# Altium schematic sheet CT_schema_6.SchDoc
size 421 x 246 mm
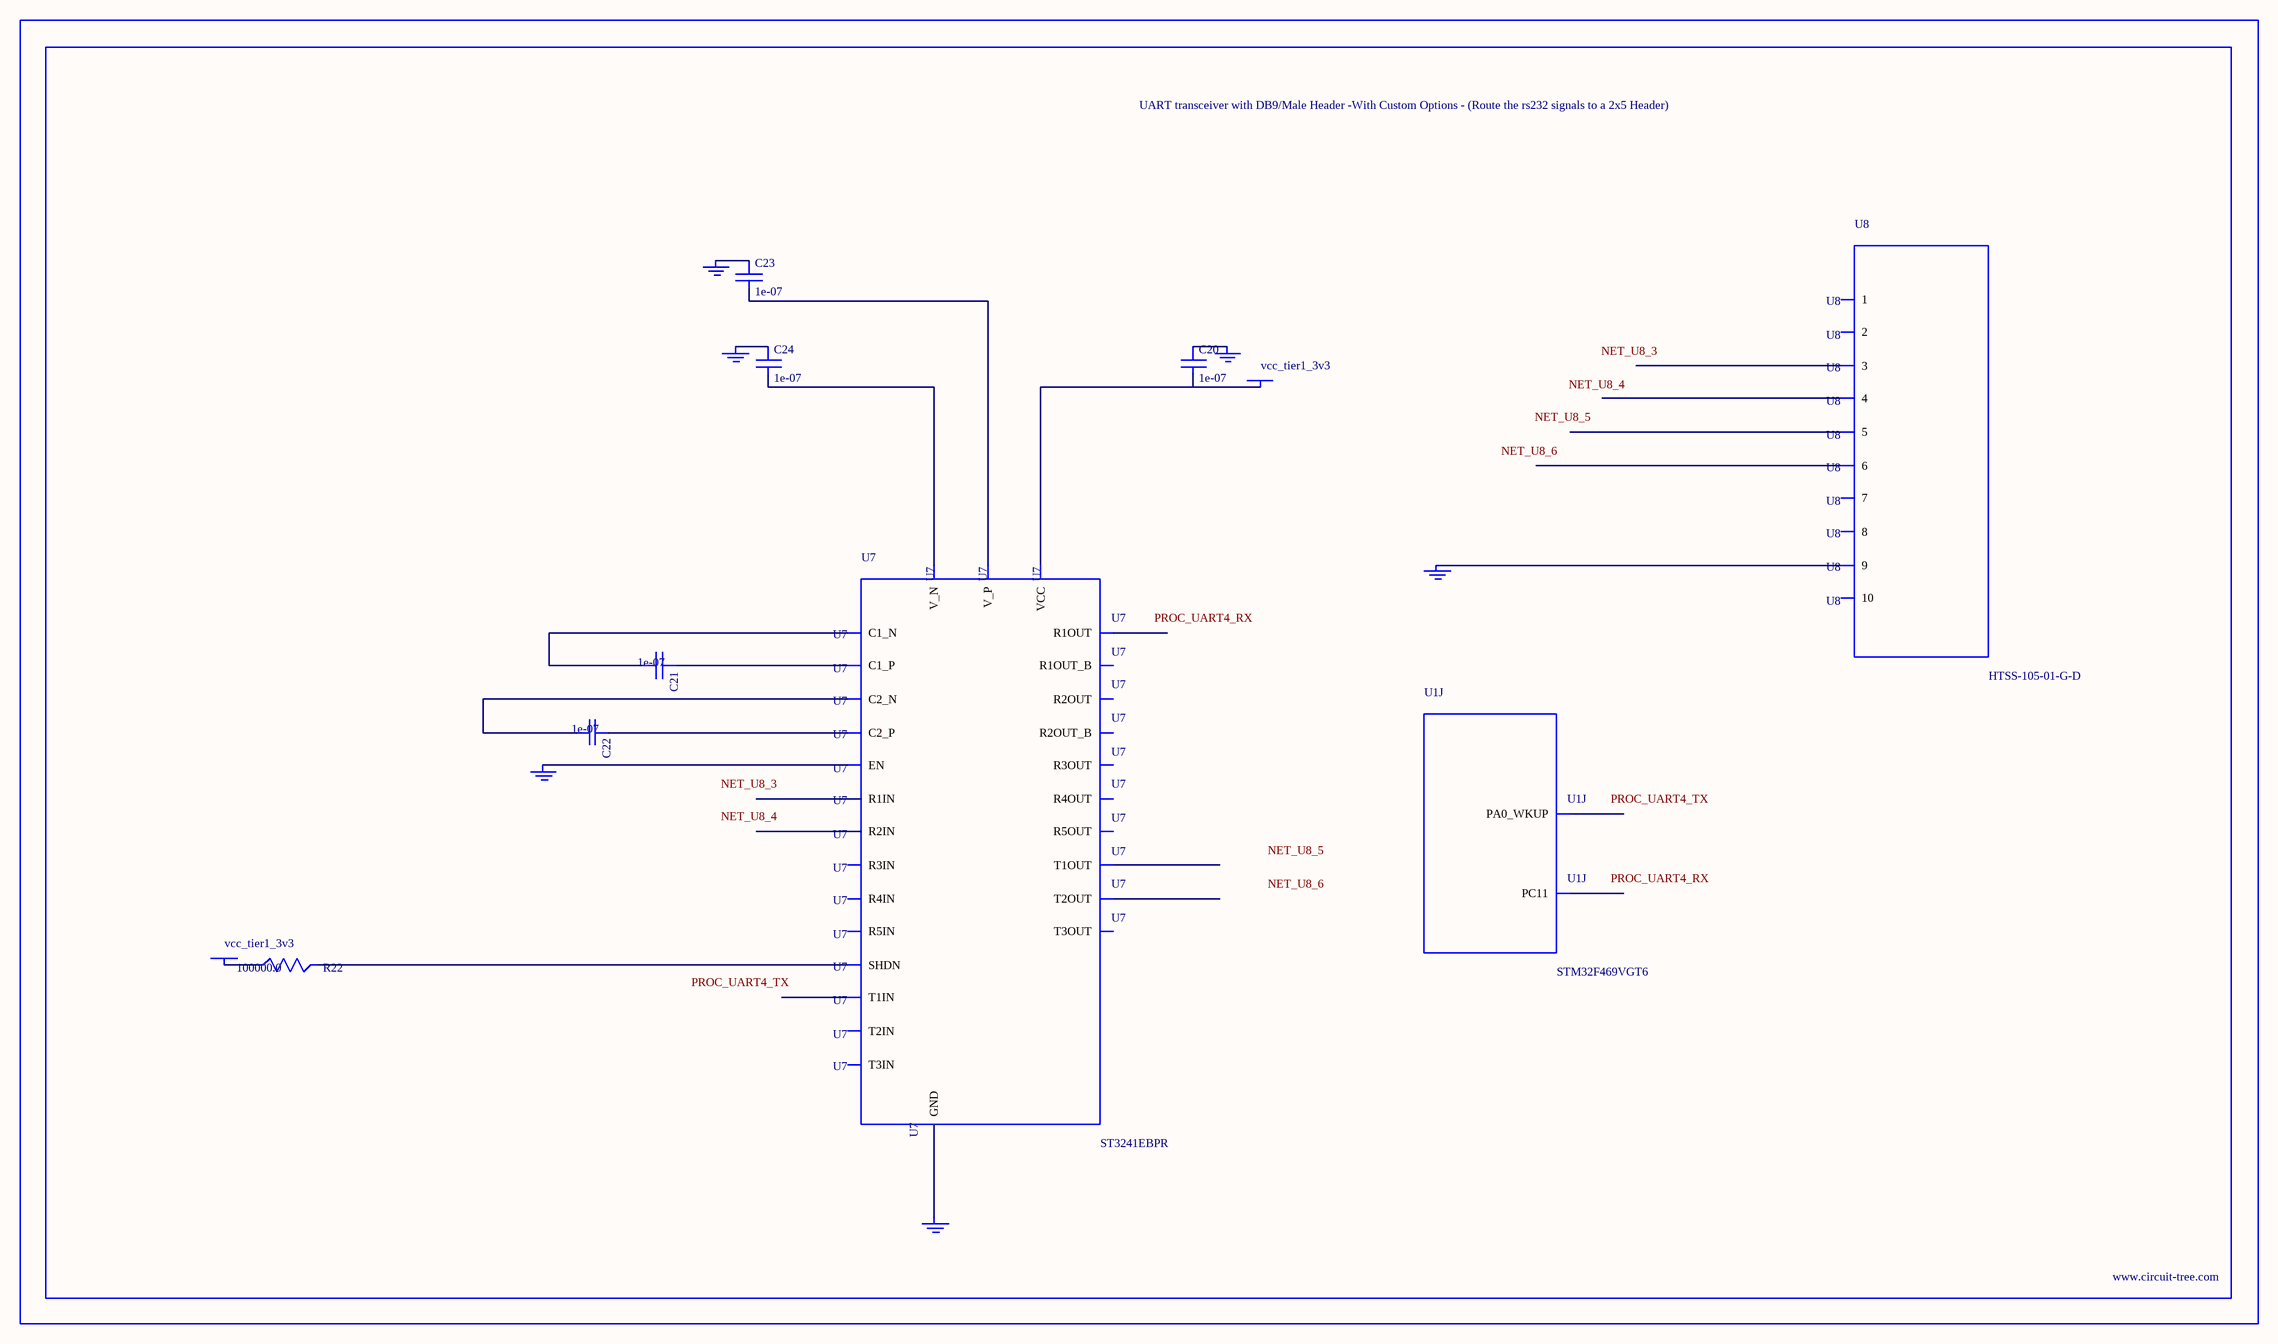
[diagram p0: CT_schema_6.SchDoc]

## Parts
BORDER5  (no value)
C20  1e-07  [C0402]
C21  1e-07  [C0402]
C22  1e-07  [C0402]
C23  1e-07  [C0402]
C24  1e-07  [C0402]
GND_INSTANCE_5_0  (no value)
GND_INSTANCE_5_1  (no value)
GND_INSTANCE_5_2  (no value)
GND_INSTANCE_5_3  (no value)
GND_INSTANCE_5_4  (no value)
GND_INSTANCE_5_5  (no value)
POWER_INSTANCE_5_0  vcc_tier1_3v3
POWER_INSTANCE_5_1  vcc_tier1_3v3
R22  100000.0  [R0603]
U1  STM32F469VGT6  [LQFP100]  (part J of 10)
U7  ST3241EBPR  [SSOP-28]
U8  HTSS-105-01-G-D  [HTSS-105-01-G-D]

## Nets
NetC20_1: C20.1 GND_INSTANCE_5_2.0(GND)
NetC20_2: C20.2 POWER_INSTANCE_5_1.0(PWR) U7.26(VCC)
NetC21_1: C21.1 U7.28(C1_P)
NetC21_2: C21.2 U7.24(C1_N)
NetC22_1: C22.1 U7.1(C2_P)
NetC22_2: C22.2 U7.2(C2_N)
NetC23_1: C23.1 GND_INSTANCE_5_3.0(GND)
NetC23_2: C23.2 U7.27(V_P)
NetC24_1: C24.1 GND_INSTANCE_5_0.0(GND)
NetC24_2: C24.2 U7.3(V_N)
NetGND_INSTANCE_5_1_0: GND_INSTANCE_5_1.0(GND) U7.23(EN)
NetGND_INSTANCE_5_4_0: GND_INSTANCE_5_4.0(GND) U7.25(GND)
NetGND_INSTANCE_5_5_0: GND_INSTANCE_5_5.0(GND) U8.9
NetPOWER_INSTANCE_5_0_0: POWER_INSTANCE_5_0.0(PWR) R22.1
NetR22_2: R22.2 U7.22(SHDN)

Not connected (* = marked no-connect by the designer): U1 19(PA0_WKUP) 82(PC11); U7 4(R1IN) 5(R2IN) 6(R3IN) 7(R4IN) 8(R5IN) 9(T1OUT) 10(T2OUT) 11(T3OUT) 12(T3IN) 13(T2IN) 14(T1IN) 15(R5OUT) 16(R4OUT) 17(R3OUT) 18(R2OUT) 19(R1OUT) 20(R2OUT_B) 21(R1OUT_B); U8 1 2 3 4 5 6 7 8 10

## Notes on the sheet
- Labels drawn without touching a wire or pin: NET_U8_3, NET_U8_4, NET_U8_5, NET_U8_6, PROC_UART4_RX, PROC_UART4_TX

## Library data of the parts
BORDER5 = BORDER_PAGE5
C20-C24 = C0402C104K3RACTU
GND_INSTANCE_5_0-GND_INSTANCE_5_5 = GND
POWER_INSTANCE_5_0 POWER_INSTANCE_5_1 = PWR
R22 = RC0603JR-07100KL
